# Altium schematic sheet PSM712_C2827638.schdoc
size 127 x 101 mm
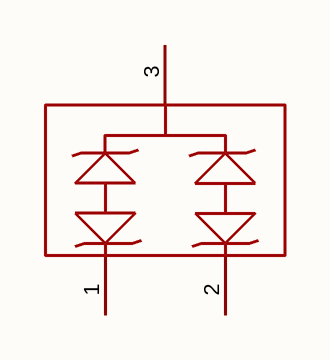
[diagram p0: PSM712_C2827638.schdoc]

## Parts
D?  psm712_c2827638  [SOT-23-3_L2.9-W1.3-P1.90-LS2.4-BL-2]  (value not drawn)

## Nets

Not connected (* = marked no-connect by the designer): D? 1 2 3

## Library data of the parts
D? = psm712_c2827638: 极性:双向;反向截止电压(Vrwm):7V；12V;钳位电压:26V；12V;峰值脉冲电流(Ipp):17A@8/20us;峰值脉冲功率(Ppp):400W@8/20us;击穿电压:13.3V；7.5V;; Manufacturer: TECH PUBLIC(台舟); ManufacturerPart: PSM712; AddInBom: yes; ModelId: 115ef394a879442d90491e6127930138; ModelName: SOT-23-3_L2.9-W1.3-P1.90-LS2.4; ModelTransform: 114.173,94.488,0,0,0,0,0,0,0; Polarity: 双向; Reverse Stand-Off Voltage (Vrwm): 7V；12V; Reverse Leakage Current (Ir): 50nA；2uA; Number of Channels: 双路; level of protection: IEC 61000-4-2；IEC 61000-4-4；IEC 61000-4-5; Type: ESD; Junction Capacitance: 45pF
